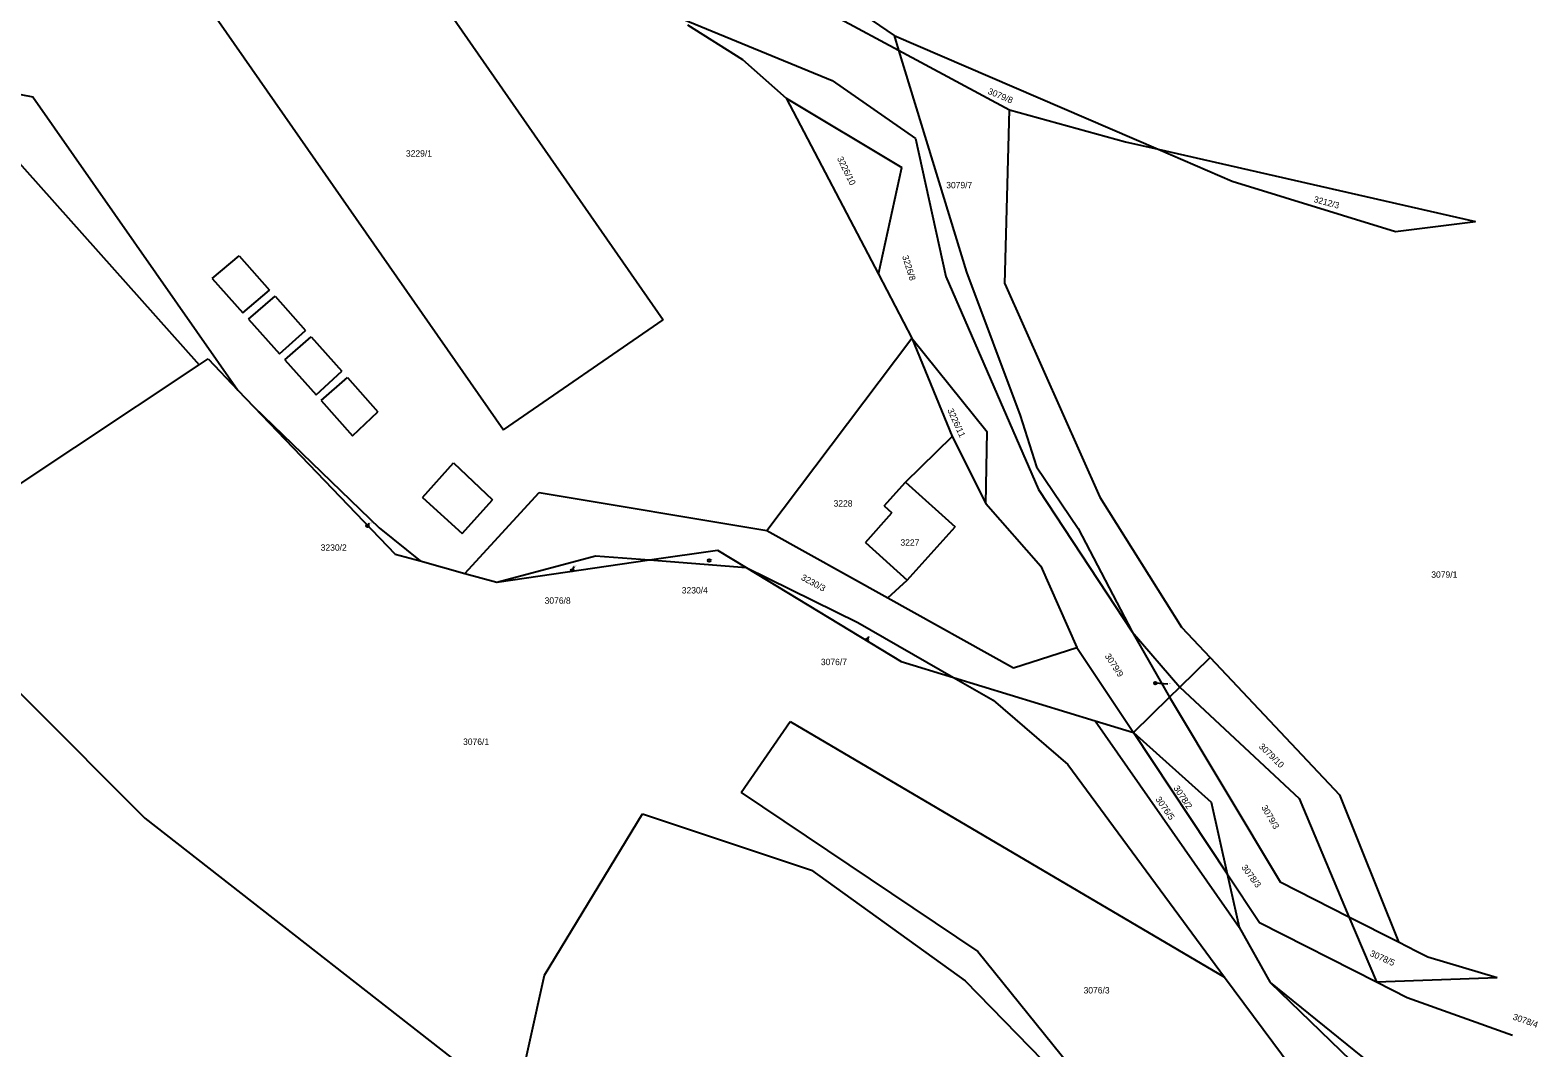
# Model space of a CAD drawing. Extents: x -722132 to -721608, y -1046877 to -1046449.
# Drawn here: x -721811.3 to -721610, y -1046745.8 to -1046609.9 of the extents above; entities that cross this region are included whole.
import ezdxf

# ---------------------------------------------------------------- set-up
doc = ezdxf.new("R2010")
doc.units = 0
for name, color, linetype in [('Vrstva 1', 7, 'Continuous'), ('Vrstva 16', 7, 'Continuous'), ('Vrstva 18', 7, 'Continuous'), ('Vrstva 19', 7, 'Continuous'), ('Vrstva 4', 7, 'Continuous'), ('Vrstva 6', 7, 'Continuous')]:
    doc.layers.add(name, color=color, linetype=linetype)

msp = doc.modelspace()

# ---------------------------------------------------------------- linework, layer by layer
at = {"layer": 'Vrstva 1'}
for points in [[(-721707.01, -1046602.99), (-721695.99, -1046610.56)], [(-721723.56, -1046609.16), (-721716.21, -1046613.8)], [(-721695.99, -1046610.56), (-721660.72, -1046625.77)], [(-721695.99, -1046610.56), (-721695.38, -1046612.55)], [(-721695.38, -1046612.55), (-721686.31, -1046642.19)], [(-721695.38, -1046612.55), (-721680.55, -1046620.52)], [(-721716.21, -1046613.8), (-721710.38, -1046618.93)], [(-721817.41, -1046617.52), (-721810.96, -1046618.75)], [(-721821.61, -1046617.74), (-721788.76, -1046654.57)], [(-721810.96, -1046618.75), (-721783.62, -1046657.93)], [(-721710.38, -1046618.93), (-721698.07, -1046642.44)], [(-721681.19, -1046643.73), (-721680.55, -1046620.52)], [(-721680.55, -1046620.52), (-721665.07, -1046624.78)], [(-721665.07, -1046624.78), (-721660.72, -1046625.77)], [(-721660.72, -1046625.77), (-721618.33, -1046635.42)], [(-721660.72, -1046625.77), (-721650.84, -1046630.03)], [(-721650.84, -1046630.03), (-721629.03, -1046636.75)], [(-721629.03, -1046636.75), (-721618.33, -1046635.42)], [(-721698.07, -1046642.44), (-721693.59, -1046650.99)], [(-721686.31, -1046642.19), (-721679.13, -1046661.35)], [(-721681.19, -1046643.73), (-721668.49, -1046672.24)], [(-721712.99, -1046676.7), (-721693.59, -1046650.99)], [(-721693.59, -1046650.99), (-721688.21, -1046664.13)], [(-721788.76, -1046654.57), (-721787.56, -1046653.77)], [(-721787.56, -1046653.77), (-721783.62, -1046657.93)], [(-721822.02, -1046676.63), (-721788.76, -1046654.57)], [(-721783.62, -1046657.93), (-721781.49, -1046660.15)], [(-721781.49, -1046660.15), (-721764.73, -1046676.35)], [(-721781.49, -1046660.15), (-721762.6, -1046679.83)], [(-721679.13, -1046661.35), (-721676.95, -1046668.2)], [(-721694.47, -1046670.25), (-721688.21, -1046664.13)], [(-721688.21, -1046664.13), (-721683.73, -1046673.07)], [(-721676.95, -1046668.2), (-721671.38, -1046676.41)], [(-721753.28, -1046682.43), (-721743.36, -1046671.63)], [(-721743.36, -1046671.63), (-721712.99, -1046676.7)], [(-721697.3, -1046673.41), (-721694.47, -1046670.25)], [(-721697.3, -1046673.41), (-721696.3, -1046674.33)], [(-721683.73, -1046673.07), (-721676.38, -1046681.46)], [(-721668.49, -1046672.24), (-721657.59, -1046689.58)], [(-721699.82, -1046678.31), (-721696.3, -1046674.33)], [(-721764.73, -1046676.35), (-721759.28, -1046680.76)], [(-721712.99, -1046676.7), (-721696.8, -1046685.69)], [(-721671.38, -1046676.41), (-721664.17, -1046690.22)], [(-721762.6, -1046679.83), (-721759.28, -1046680.76)], [(-721749.03, -1046683.61), (-721735.87, -1046680.05)], [(-721735.87, -1046680.05), (-721728.62, -1046680.62)], [(-721699.82, -1046678.31), (-721694.22, -1046683.33)], [(-721759.28, -1046680.76), (-721753.28, -1046682.43)], [(-721749.03, -1046683.61), (-721728.62, -1046680.62)], [(-721728.62, -1046680.62), (-721715.71, -1046681.64)], [(-721715.71, -1046681.64), (-721695.04, -1046694.18)], [(-721715.71, -1046681.64), (-721700.83, -1046688.98)], [(-721676.38, -1046681.46), (-721671.56, -1046692.32)], [(-721827.2, -1046683.92), (-721796.01, -1046715.1)], [(-721753.28, -1046682.43), (-721749.03, -1046683.61)], [(-721696.8, -1046685.69), (-721694.22, -1046683.33)], [(-721696.8, -1046685.69), (-721680.04, -1046695.05)], [(-721700.83, -1046688.98), (-721688.04, -1046696.33)], [(-721657.59, -1046689.58), (-721653.77, -1046693.64)], [(-721664.17, -1046690.22), (-721657.81, -1046697.59)], [(-721664.17, -1046690.22), (-721659.2, -1046698.95)], [(-721695.04, -1046694.18), (-721688.04, -1046696.33)], [(-721680.04, -1046695.05), (-721671.56, -1046692.32)], [(-721671.56, -1046692.32), (-721664.02, -1046703.68)], [(-721657.81, -1046697.59), (-721653.77, -1046693.64)], [(-721653.77, -1046693.64), (-721636.52, -1046711.99)], [(-721688.04, -1046696.33), (-721682.76, -1046699.36)], [(-721688.04, -1046696.33), (-721669.14, -1046702.11)], [(-721659.2, -1046698.95), (-721657.81, -1046697.59)], [(-721657.81, -1046697.59), (-721641.88, -1046712.48)], [(-721682.76, -1046699.36), (-721672.78, -1046707.96)], [(-721664.02, -1046703.68), (-721659.2, -1046698.95)], [(-721659.2, -1046698.95), (-721644.42, -1046723.62)], [(-721716.4, -1046711.66), (-721709.87, -1046702.18)], [(-721709.87, -1046702.18), (-721651.87, -1046736.33)], [(-721669.14, -1046702.11), (-721664.02, -1046703.68)], [(-721669.14, -1046702.11), (-721649.91, -1046729.66)], [(-721664.02, -1046703.68), (-721651.51, -1046722.54)], [(-721672.78, -1046707.96), (-721651.87, -1046736.33)], [(-721716.4, -1046711.66), (-721684.82, -1046732.93)], [(-721636.52, -1046711.99), (-721628.65, -1046731.61)], [(-721641.88, -1046712.48), (-721635.26, -1046728.27)], [(-721796.01, -1046715.1), (-721746.59, -1046753.73)], [(-721742.65, -1046736.09), (-721729.58, -1046714.52)], [(-721729.58, -1046714.52), (-721707.03, -1046722.06)], [(-721707.03, -1046722.06), (-721686.47, -1046736.84)], [(-721651.51, -1046722.54), (-721647.18, -1046729.06)], [(-721651.51, -1046722.54), (-721649.91, -1046729.66)], [(-721644.42, -1046723.62), (-721635.26, -1046728.27)], [(-721635.26, -1046728.27), (-721628.65, -1046731.61)], [(-721649.91, -1046729.66), (-721645.76, -1046737.04)], [(-721647.18, -1046729.06), (-721631.59, -1046736.97)], [(-721628.65, -1046731.61), (-721626.22, -1046732.85)], [(-721684.82, -1046732.93), (-721661.26, -1046762.13)], [(-721626.22, -1046732.85), (-721624.7, -1046733.62)], [(-721624.7, -1046733.62), (-721615.47, -1046736.37)], [(-721746.59, -1046753.73), (-721742.65, -1046736.09)], [(-721651.87, -1046736.33), (-721637.78, -1046755.26)], [(-721686.47, -1046736.84), (-721664.08, -1046759.87)], [(-721645.76, -1046737.04), (-721620.31, -1046761.66)], [(-721645.76, -1046737.04), (-721632.49, -1046747.8)], [(-721631.59, -1046736.97), (-721627.46, -1046739.06)], [(-721627.46, -1046739.06), (-721613.39, -1046744.1)]]:
    msp.add_lwpolyline(points, dxfattribs=at)
at = {"layer": 'Vrstva 16'}
for points in [[(-721766.09, -1046675.74), (-721766.3, -1046676.05)], [(-721738.76, -1046681.49), (-721738.96, -1046682.01)], [(-721720.64, -1046680.61), (-721720.67, -1046680.69)], [(-721699.35, -1046690.87), (-721699.6, -1046691.27)], [(-721659.45, -1046697.21), (-721661.1, -1046697.08)]]:
    msp.add_lwpolyline(points, dxfattribs=at)
for centre in [(-721766.3, -1046676.05), (-721738.96, -1046682.01), (-721720.67, -1046680.69), (-721699.6, -1046691.27), (-721661.1, -1046697.08)]:
    msp.add_circle(centre, 0.175, dxfattribs=at)
at = {"layer": 'Vrstva 4'}
for points in [[(-721770.14, -1046586.22), (-721726.8, -1046648.56)], [(-721791.55, -1046600.86), (-721748.12, -1046663.26)], [(-721787.02, -1046643.01), (-721783.44, -1046640.01)], [(-721783.44, -1046640.01), (-721779.36, -1046644.59)], [(-721787.02, -1046643.01), (-721782.92, -1046647.63)], [(-721782.92, -1046647.63), (-721779.36, -1046644.59)], [(-721782.18, -1046648.44), (-721778.63, -1046645.41)], [(-721778.63, -1046645.41), (-721774.57, -1046649.97)], [(-721782.18, -1046648.44), (-721778.03, -1046653.1)], [(-721748.12, -1046663.26), (-721726.8, -1046648.56)], [(-721778.03, -1046653.1), (-721774.57, -1046649.97)], [(-721777.34, -1046653.88), (-721773.81, -1046650.81)], [(-721773.81, -1046650.81), (-721769.71, -1046655.42)], [(-721777.34, -1046653.88), (-721773.15, -1046658.58)], [(-721773.15, -1046658.58), (-721769.71, -1046655.42)], [(-721772.47, -1046659.34), (-721768.97, -1046656.25)], [(-721768.97, -1046656.25), (-721764.89, -1046660.83)], [(-721772.47, -1046659.34), (-721768.29, -1046664.04)], [(-721768.29, -1046664.04), (-721764.89, -1046660.83)], [(-721758.97, -1046672.26), (-721754.79, -1046667.66)], [(-721754.79, -1046667.66), (-721749.62, -1046672.57)], [(-721694.47, -1046670.25), (-721687.83, -1046676.21)], [(-721758.97, -1046672.26), (-721753.66, -1046677.08)], [(-721753.66, -1046677.08), (-721749.62, -1046672.57)], [(-721694.22, -1046683.33), (-721687.83, -1046676.21)]]:
    msp.add_lwpolyline(points, dxfattribs=at)
at = {"layer": 'Vrstva 6'}
for points in [[(-721729.02, -1046606.4), (-721704.27, -1046616.59)], [(-721703.18, -1046608.36), (-721695.38, -1046612.55)], [(-721704.27, -1046616.59), (-721693.1, -1046624.32)], [(-721710.38, -1046618.93), (-721694.96, -1046628.22)], [(-721693.1, -1046624.32), (-721689.07, -1046642.77)], [(-721698.07, -1046642.44), (-721694.96, -1046628.22)], [(-721689.07, -1046642.77), (-721676.71, -1046671.19)], [(-721693.59, -1046650.99), (-721683.54, -1046663.53)], [(-721683.73, -1046673.07), (-721683.54, -1046663.53)], [(-721676.71, -1046671.19), (-721664.17, -1046690.22)], [(-721728.62, -1046680.62), (-721719.57, -1046679.3)], [(-721719.57, -1046679.3), (-721715.71, -1046681.64)], [(-721664.02, -1046703.68), (-721653.65, -1046712.95)], [(-721653.65, -1046712.95), (-721651.51, -1046722.54)], [(-721635.26, -1046728.27), (-721631.59, -1046736.97)], [(-721631.59, -1046736.97), (-721615.47, -1046736.37)]]:
    msp.add_lwpolyline(points, dxfattribs=at)

# ---------------------------------------------------------------- texts
at = {"layer": 'Vrstva 16'}
for s, p in [('3230/2', (-721772.54, -1046679.39)), ('3076/8', (-721742.64, -1046686.47)), ('3230/4', (-721724.33, -1046685.1)), ('3076/7', (-721705.75, -1046694.67))]:
    msp.add_text(s, height=0.85, dxfattribs=at).set_placement(p)
msp.add_text('3079/9', height=0.85, rotation=303.3059, dxfattribs=at).set_placement((-721667.89, -1046693.45))
at = {"layer": 'Vrstva 18'}
for s, rotation, p in [('3079/8', 336.9776, (-721683.54, -1046618.33)), ('3226/10', 296.0987, (-721703.62, -1046626.99)), ('3212/3', 344.8843, (-721640.02, -1046632.81)), ('3226/8', 287.4355, (-721694.91, -1046640.08)), ('3226/11', 294.4376, (-721688.89, -1046660.61)), ('3230/3', 331.4146, (-721708.48, -1046683.22)), ('3079/10', 315.7534, (-721647.35, -1046705.62)), ('3076/5', 304.805, (-721661.13, -1046712.59)), ('3078/2', 303.3293, (-721658.72, -1046711.09)), ('3079/3', 300.2998, (-721646.98, -1046713.67)), ('3078/3', 306.6573, (-721649.66, -1046721.7)), ('3078/5', 335.7492, (-721632.53, -1046733.46)), ('3078/4', 340.3727, (-721613.45, -1046741.97))]:
    msp.add_text(s, height=0.85, rotation=rotation, dxfattribs=at).set_placement(p)
for s, height, p in [('3229/1', 0.85, (-721761.16, -1046626.75)), ('3079/7', 0.85, (-721689.02, -1046630.98)), ('3228', 0.85, (-721704.06, -1046673.49)), ('3230/2', 0.1, (-721766.09, -1046675.74)), ('3076/8', 0.1, (-721738.76, -1046681.49)), ('3230/4', 0.1, (-721720.64, -1046680.61)), ('3079/1', 0.85, (-721624.25, -1046683)), ('3076/7', 0.1, (-721699.35, -1046690.87)), ('3079/9', 0.1, (-721659.45, -1046697.21)), ('3076/1', 0.85, (-721753.53, -1046705.32)), ('3076/3', 0.85, (-721670.68, -1046738.52))]:
    msp.add_text(s, height=height, dxfattribs=at).set_placement(p)
at = {"layer": 'Vrstva 19'}
msp.add_text('3227', height=0.85, dxfattribs=at).set_placement((-721695.13, -1046678.71))

doc.saveas('drawing.dxf')
